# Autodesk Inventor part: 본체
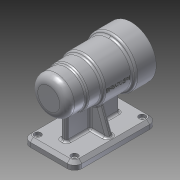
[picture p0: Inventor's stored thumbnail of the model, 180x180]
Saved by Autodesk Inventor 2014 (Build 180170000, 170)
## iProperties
Created: 2016-06
Part Number: 본체
Material: 알루미늄 6061
Document SubType Name: Modeling
Designer: USER
Density: 2.71 g/cm^3
Appearance: 알루미늄 - 평지
Mass: 671.062 g
Surface Area: 646.965 cm^2
Volume: 247.624 cm^3
Author: USER
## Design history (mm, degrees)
sketch "스케치1"
  geometry: L1 (0, 0)-(112, 0); L2 (0, 0)-(0, 25); L3 (0, 25)-(25, 25); L4 (25, 25)-(25, 27); L5 (25, 27)-(45, 27); L6 (45, 27)-(45, 30); L7 (45, 30)-(84, 30); L8 (84, 30)-(84, 34); L9 (84, 34)-(112, 34); L10 (112, 34)-(112, 0)
  constraints: 20 end point, 6 parallel, 3 perpendicular, 1 horizontal
  dimensions: "d0" = 112 distance of L1.start L1.end; "d2" = 50 diameter of L3 L1; "d3" = 54 diameter of L5 L1; "d4" = 60 diameter of L7 L1; "d5" = 68 diameter of L9 L1; "d6" = 25 distance of L2.end L3.end; "d7" = 45 distance between parallel lines of L6 L2; "d8" = 84 distance between parallel lines of L8 L2
revolve "회전1" sketch "스케치1" stored, may be unused: angle "d9" = 90 deg
fillet "모깎기1" dims "d10" = 3
fillet "모깎기2" dims "d11" = 3
fillet "모깎기3" dims "d12" = 10
sketch "스케치2"
  geometry: C1 r 34 at (0, 0) reference; 1 further point
  constraints: 1 coincident
hole "구멍1" sketch "스케치2" at (0, 0) diameter "d13" = 42; stored, may be unused: countersink angle "d17" = 90 deg, drill point angle "d19" = 0 deg; dims "d14" = 6, "d15" = 4, "d16" = 2, "d18" = 15
sketch "스케치3"
  geometry: C1 r 21 at (0, 0) reference; 1 further point
  constraints: 1 coincident
hole "구멍2" sketch "스케치3" at (0, 0) diameter "d20" = 48; stored, may be unused: countersink angle "d24" = 90 deg, drill point angle "d26" = 0 deg; dims "d21" = 6, "d22" = 4, "d23" = 2, "d25" = 54
sketch "스케치4"
  geometry: C1 r 24 at (0, 0) reference; 1 further point
  constraints: 1 coincident
hole "구멍3" sketch "스케치4" at (0, 0) diameter "d27" = 35; stored, may be unused: countersink angle "d31" = 90 deg, drill point angle "d33" = 0 deg; dims "d28" = 6, "d29" = 42, "d30" = 12, "d32" = 30
sketch "스케치5"
  geometry: C1 r 17.5 at (0, 0) reference; 1 further point
  constraints: 1 coincident
hole "구멍4" sketch "스케치5" at (0, 0) diameter "d34" = 21; stored, may be unused: countersink angle "d38" = 90 deg, drill point angle "d40" = 0 deg; dims "d35" = 6, "d36" = 32, "d37" = 4, "d39" = 7
chamfer "모따기1" distance "d41" = 1; stored, may be unused: second distance "d42" = 2, angle "d43" = 45 deg
fillet "모깎기6" dims "d46" = 0.3
fillet "모깎기7" dims "d47" = 3
node "작업 평면1"
sketch "스케치9"
  geometry: L1 (-112, 34)-(-112, -34) reference; L2 (0, 15)-(0, -15) reference; L3 (-112, 35)-(-112, -35); L4 (-112, -35)-(0, -35); L5 (0, -35)-(0, 35); L6 (0, 35)-(-112, 35); L7 (-112, 0)-(0, 0); 3 further points
  constraints: 10 end point, 4 midpoint, 2 perpendicular, 1 coincident, 1 collinear, 1 parallel, 1 vertical alignment
  dimensions: "d51" = 70 distance of L3.start L3.end; "d52" = 112 distance of L3.end L4.end; "d53" = 70 distance of L4.end L5.end
extrude "돌출1" join sketch "스케치9" distance "d54" = 10; taper "d55" = 0 deg
sketch "스케치10"
  geometry: L1 (-112, 35)-(-112, -35) reference; L2 (0, 35)-(-112, 35) reference; 2 further points
  dimensions: "d56" = 10 distance from line of L2 point (-102, 25); "d57" = 10 distance from line of L1 point (-102, 25)
hole "구멍5" sketch "스케치10" at (-102, 25) diameter "d58" = 5; stored, may be unused: countersink angle "d62" = 90 deg, drill point angle "d64" = 0 deg; dims "d59" = 6, "d60" = 9, "d61" = 4, "d63" = 7
fillet "모깎기8" dims "d71" = 10
chamfer "모따기2" distance "d72" = 4; stored, may be unused: second distance "d73" = 2, angle "d74" = 45 deg
sketch "스케치12"
  geometry: L1 (-102, 31)-(-10, 31) reference; L2 (-92, 4)-(-92, -4); L3 (-92, -4)-(-20, -4); L4 (-20, -4)-(-20, 4); L5 (-20, 4)-(-20, -4); L6 (-20, 4)-(-92, 4); L7 (-112, 25)-(-112, -25) reference; L8 (0, -25)-(0, 25) reference; 3 further points
  constraints: 10 end point, 2 midpoint, 2 parallel, 2 perpendicular, 1 horizontal alignment
  dimensions: "d79" = 8 distance of L2.start L2.end; "d80" = 8 distance of L4.end L3.end; "d81" = 20 distance between parallel lines of L7 L2; "d82" = 20 distance between parallel lines of L8 L4
extrude "돌출3" join sketch "스케치12" stored distance "d83" = 8; taper "d84" = 0 deg
node "작업 평면2"
sketch "스케치13"
  geometry: L1 (-10, 0)-(-10, 50) reference; L2 (-10, -3)-(-44.32, 9.491); L3 (-10, 53)-(-44.32, 40.509); L4 (-10, -4.5)-(-10, 4.5) reference; L5 (-10, 45.5)-(-10, 54.5) reference; L6 (-6, 60)-(0, 60) reference; L7 (0, -10)-(-6, -10) reference; A1 r 30 centre (-70, 25) between (-40.268, 29) and (-40.268, 21) reference; 4 further points
  constraints: 4 end point, 2 point on circle, 2 point on line, 4 other
  dimensions: "d85" = 7 distance from line of L6 L3.start; "d86" = 7 distance from line of L7 L2.start; "d87" = 110 deg angle of L4 L2; "d88" = 110 deg angle of L5 L3
  node "투영된 루프1"
feature "리브1" dims "d89" = 1, "d90" = 8, "d91" = 0, "d92" = 0, "d93" = 1, "d94" = 1
feature "리브2" dims "d95" = 1, "d96" = 8, "d97" = 0, "d98" = 0, "d99" = 1, "d100" = 1
fillet "모깎기9" dims "d101" = 3
fillet "모깎기10" dims "d102" = 3
sketch "스케치14" dims "d103" = 52
  geometry: C1 r 34 at (0, 0) reference; C2 r 22 at (0, 0) reference; 2 further points
  constraints: 2 horizontal alignment, 1 coincident, 2 other
hole "구멍6" sketch "스케치14" at (26, 0) diameter "d104" = 3.242; stored, may be unused: countersink angle "d108" = 90 deg, drill point angle "d110" = 118 deg; dims "d105" = 8, "d106" = 9, "d107" = 4, "d109" = 11
node "작업 평면3"
sketch "스케치15"
  geometry: L1 (47.5, -34)-(47.5, 34) reference; 2 further points
  constraints: 1 horizontal alignment, 1 other
  dimensions: "d114" = 48 distance from line of L1 point (-0.5, 0)
feature "엠보싱1" sketch "스케치15" dims "d0" = 112, "d2" = 50, "d3" = 54, "d4" = 60, "d5" = 68, "d6" = 25, "d7" = 45, "d8" = 84, "d115" = 0.5, "d116" = 0
node "솔리드1"
pattern_linear "직사각형 패턴1" dims "d67" = 92
pattern_circular "원형 패턴1" dims angle "d112" = 360 deg
